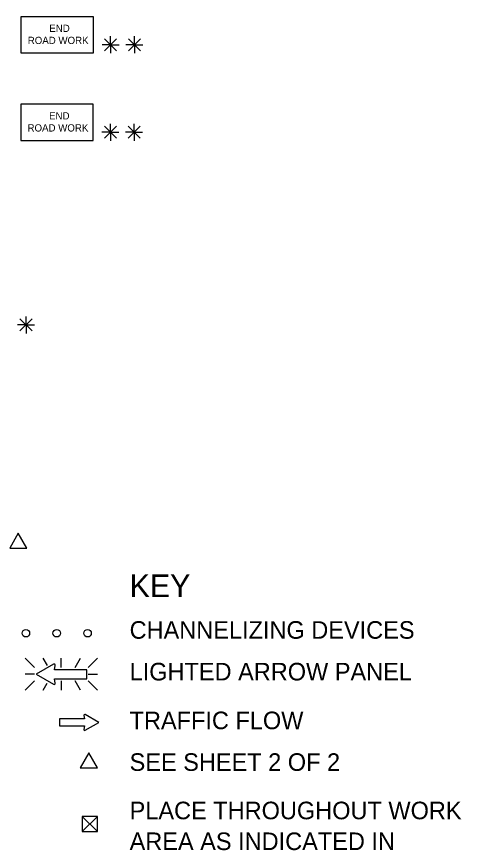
# Model space of a CAD drawing. Extents: x 16729 to 18500, y 5737 to 6974.
# Drawn here: x 17189.6 to 17424.7, y 6399.5 to 6840.6 of the extents above; entities that cross this region are included whole.
import ezdxf

# ---------------------------------------------------------------- set-up
doc = ezdxf.new("R2010")
doc.units = 0
for name, color, linetype in [('MT_SCRATCH_LEVEL_E', 7, 'Continuous'), ('TRAFFIC_SIGNS_PR', 7, 'Continuous'), ('TYPICAL_TEXT_DIMEN_EX', 7, 'Continuous'), ('TYPICAL_TEXT_DIMEN_PR', 7, 'Continuous')]:
    doc.layers.add(name, color=color, linetype=linetype)

msp = doc.modelspace()

# ---------------------------------------------------------------- linework, layer by layer
at = {"layer": 'MT_SCRATCH_LEVEL_E'}
for p, q in [((17225.13, 6470.85), (17225.44, 6469.07)), ((17233.05, 6467.22), (17225.81, 6471.33)), ((17225.44, 6469.07), (17212.19, 6469.07)), ((17212.19, 6469.07), (17212.19, 6465.33)), ((17225.81, 6463.07), (17233.05, 6467.22)), ((17212.19, 6465.33), (17225.44, 6465.33)), ((17225.44, 6465.33), (17225.13, 6463.55))]:
    msp.add_line(p, q, dxfattribs=at)
for centre, start, end in [((17225.59, 6470.93), 60.4248, 189.9638), ((17225.59, 6463.48), 170.0362, 299.7731)]:
    msp.add_arc(centre, 0.463, start, end, dxfattribs=at)
at = {"layer": 'TRAFFIC_SIGNS_PR'}
for p, q in [((17194.12, 6501.23), (17199.05, 6496.3)), ((17205.88, 6497.41), (17203.67, 6501.23)), ((17213.2, 6496.3), (17213.2, 6501.23)), ((17220.44, 6496.3), (17223.28, 6501.23)), ((17227.35, 6496.3), (17232.28, 6501.23)), ((17199.05, 6492.74), (17194.12, 6492.74)), ((17227.35, 6492.74), (17232.28, 6492.74)), ((17194.12, 6484.25), (17199.05, 6489.19)), ((17213.2, 6489.19), (17213.2, 6484.25)), ((17223.33, 6484.25), (17220.48, 6489.19)), ((17227.35, 6489.19), (17232.28, 6484.25)), ((17203.63, 6484.25), (17205.74, 6487.91))]:
    msp.add_line(p, q, dxfattribs=at)
for points in [[(17191.84, 6821.42), (17230.24, 6821.42), (17230.24, 6840.62), (17191.84, 6840.62)], [(17191.72, 6775.12), (17230.12, 6775.12), (17230.12, 6794.32), (17191.72, 6794.32)]]:
    msp.add_lwpolyline(points, close=True, dxfattribs=at)
for points in [[(17209.13, 6498.02), (17199.84, 6492.74), (17209.13, 6487.42)], [(17210, 6488.05), (17209.6, 6490.32), (17226.62, 6490.32), (17226.62, 6495.12), (17209.6, 6495.12), (17210.01, 6497.4)]]:
    msp.add_lwpolyline(points, dxfattribs=at)
for centre in [(17194.46, 6514.43), (17210.76, 6514.43), (17227.06, 6514.43)]:
    msp.add_circle(centre, 2, dxfattribs=at)
for centre, radius, start, end in [((17209.42, 6497.49), 0.598, 350.7308, 118.8916), ((17209.41, 6487.94), 0.597, 241.4833, 9.9593)]:
    msp.add_arc(centre, radius, start, end, dxfattribs=at)
at = {"layer": 'TYPICAL_TEXT_DIMEN_PR'}
for p, q in [((17236.07, 6828.98), (17242.45, 6822.61)), ((17242.45, 6828.98), (17236.07, 6822.61)), ((17239.26, 6825.8), (17239.26, 6830.25)), ((17248.63, 6828.98), (17255, 6822.61)), ((17255, 6828.98), (17248.63, 6822.61)), ((17251.81, 6825.8), (17251.81, 6830.25)), ((17239.26, 6825.8), (17234.73, 6825.8)), ((17239.26, 6825.8), (17242.45, 6825.8)), ((17239.26, 6825.8), (17243.74, 6825.8)), ((17239.26, 6825.8), (17239.26, 6821.3)), ((17251.81, 6825.8), (17247.28, 6825.8)), ((17251.81, 6825.8), (17255, 6825.8)), ((17251.81, 6825.8), (17256.29, 6825.8)), ((17251.81, 6825.8), (17251.81, 6821.3)), ((17239.15, 6779.49), (17239.15, 6783.94)), ((17251.7, 6779.49), (17251.7, 6783.94)), ((17239.15, 6779.49), (17234.62, 6779.49)), ((17235.96, 6782.68), (17242.33, 6776.3)), ((17242.33, 6782.68), (17235.96, 6776.3)), ((17239.15, 6779.49), (17242.33, 6779.49)), ((17239.15, 6779.49), (17243.62, 6779.49)), ((17239.15, 6779.49), (17239.15, 6774.99)), ((17251.7, 6779.49), (17247.17, 6779.49)), ((17254.89, 6782.68), (17248.51, 6776.3)), ((17248.52, 6782.68), (17254.89, 6776.3)), ((17251.7, 6779.49), (17254.89, 6779.49)), ((17251.7, 6779.49), (17256.18, 6779.49)), ((17251.7, 6779.49), (17251.7, 6774.99)), ((17191.35, 6680.76), (17197.72, 6674.38)), ((17197.72, 6680.76), (17191.35, 6674.38)), ((17194.54, 6677.57), (17194.54, 6682.03)), ((17194.54, 6677.57), (17190.01, 6677.57)), ((17194.54, 6677.57), (17197.72, 6677.57)), ((17194.54, 6677.57), (17199.01, 6677.57)), ((17194.54, 6677.57), (17194.54, 6673.07)), ((17224.29, 6417.48), (17232.29, 6409.48)), ((17224.29, 6409.48), (17232.29, 6417.48))]:
    msp.add_line(p, q, dxfattribs=at)
for points in [[(17190.44, 6567.27), (17185.92, 6559.44), (17194.97, 6559.44)], [(17227.76, 6451.05), (17223.24, 6443.21), (17232.29, 6443.21)], [(17224.29, 6417.48), (17224.29, 6409.48), (17232.29, 6409.48), (17232.29, 6417.48)]]:
    msp.add_lwpolyline(points, close=True, dxfattribs=at)

# ---------------------------------------------------------------- texts
at = {"layer": 'TRAFFIC_SIGNS_PR'}
for s, p in [('END', (17206.84, 6832.55)), ('ROAD WORK', (17195.45, 6826.16)), ('END', (17206.73, 6786.24)), ('ROAD WORK', (17195.33, 6779.86))]:
    msp.add_text(s, height=3.831, dxfattribs=at).set_placement(p)
at = {"layer": 'TYPICAL_TEXT_DIMEN_EX'}
for s, height, p in [('KEY', 12, (17249.3, 6533.54)), ('CHANNELIZING DEVICES', 9.3, (17249.3, 6511.49)), ('LIGHTED ARROW PANEL', 9.3, (17249.3, 6489.44)), ('TRAFFIC FLOW', 9.3, (17249.3, 6463.64)), ('SEE SHEET 2 OF 2', 9.3, (17249.3, 6441.59)), ('PLACE THROUGHOUT WORK', 9.3, (17249.3, 6415.98)), ('AREA AS INDICATED IN', 9.3, (17249.3, 6399.68))]:
    msp.add_text(s, height=height, dxfattribs=at).set_placement(p)

doc.saveas('drawing.dxf')
